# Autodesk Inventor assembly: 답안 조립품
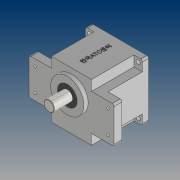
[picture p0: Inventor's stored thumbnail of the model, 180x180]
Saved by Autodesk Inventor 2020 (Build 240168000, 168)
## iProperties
Created: 2020-07
Part Number: 답안 조립품
Document SubType Name: Assembly
Designer: PC312-
Author: PC312-
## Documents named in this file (10)
- C:\Users\PC312-\Desktop\700718V1004\답안 조립품.iam
- C:\Users\PC312-\Desktop\700718V1004\본체.ipt
- C:\Users\PC312-\Desktop\700718V1004\커버.ipt
- C:\Users\PC312-\Desktop\700718V1004\베어링 608.ipt
- C:\Users\PC312-\Desktop\700718V1004\서브 축.ipt
- C:\Users\PC312-\Desktop\700718V1004\베어링 6003.ipt
- C:\Users\PC312-\Desktop\700718V1004\오일 실 17 32 8.ipt
- C:\Users\PC312-\Desktop\700718V1004\메인 축.ipt
- C:\Users\PC312-\Desktop\700718V1004\오일 실 8 22 7.ipt
- C:\Users\PC312-\Desktop\700718V1004\볼트 M4.ipt
